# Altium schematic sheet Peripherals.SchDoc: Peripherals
size A4; Date: 01-DEC-2013; CompanyName: STMicroelectronics; Organization: Microcontrollers Division; Address1: 12, Rue Jules HOROWITZ; Address2: 38019 Grenoble; Address3: FRANCE; DocumentNumber: MB1263; Revision: C-04; SheetNumber: 11; SheetTotal: 11; Project: STM32MP157-EVAL
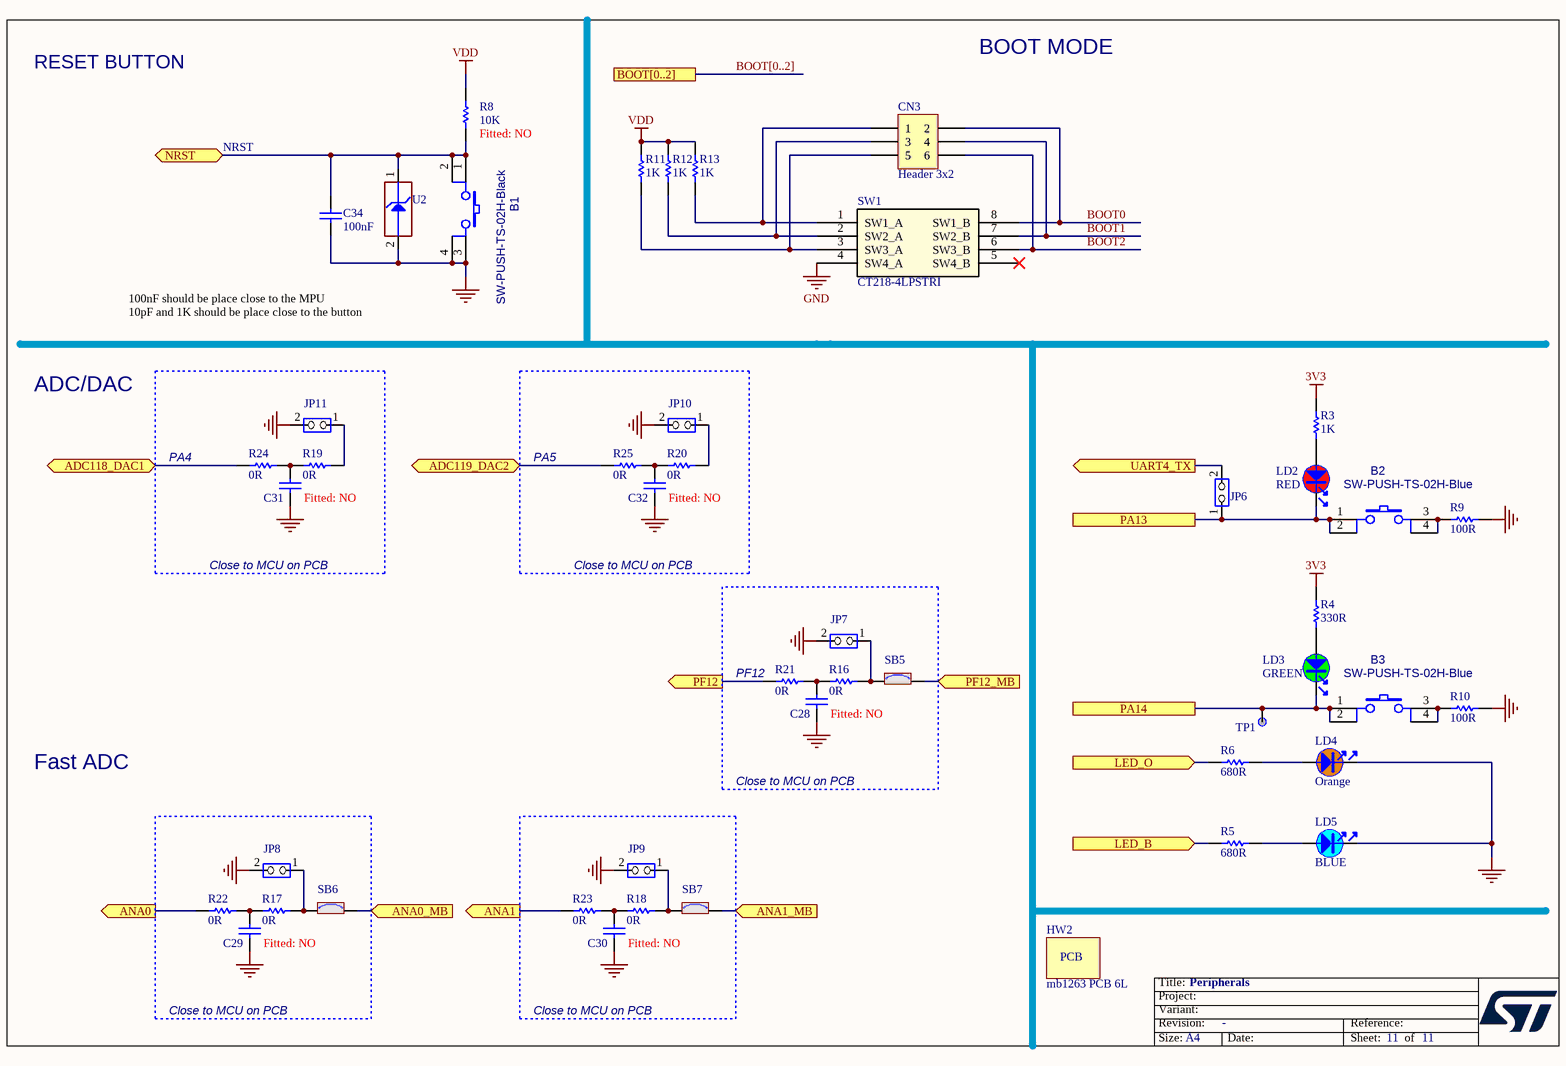
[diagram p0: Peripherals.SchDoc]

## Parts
B1  SW-PUSH-TS-02H-Black  [SWI_JIUBABA_C-TS-02H-2-5-K-V-T_R_BLACK]
B2  SW-PUSH-TS-02H-Blue  [SWI_JIUBABA_C-TS-02H-2-5-B-V-T_R_BLUE]
B3  SW-PUSH-TS-02H-Blue  [SWI_JIUBABA_C-TS-02H-2-5-B-V-T_R_BLUE]
C28  Fitted: NO  [C0402]  (hidden comment: 100nF)
C29  Fitted: NO  [C0402]  (hidden comment: 100nF)
C30  Fitted: NO  [C0402]  (hidden comment: 100nF)
C31  Fitted: NO  [C0402]  (hidden comment: 100nF)
C32  Fitted: NO  [C0402]  (hidden comment: 100nF)
C34  100nF  [C0402]
CN3  Header 3x2  [CON_SAMTEC_TSW-103-07-X-D]
HW2  mb1263 PCB 6L  (mechanical)
JP6  Jumper_2.54mm  [CON_SAMTEC_TSW-102-07-G-S]  (value not drawn)
JP7  Jumper_2.54mm  [CON_SAMTEC_TSW-102-07-G-S]  (value not drawn)
JP8  Jumper_2.54mm  [CON_SAMTEC_TSW-102-07-G-S]  (value not drawn)
JP9  Jumper_2.54mm  [CON_SAMTEC_TSW-102-07-G-S]  (value not drawn)
JP10  Jumper_2.54mm  [CON_SAMTEC_TSW-102-07-G-S]  (value not drawn)
JP11  Jumper_2.54mm  [CON_SAMTEC_TSW-102-07-G-S]  (value not drawn)
LD2  value RED  [LED_0603_RED]  (hidden comment: LED_red)
LD3  value GREEN  [LED_0603_GREEN]  (hidden comment: LED_green)
LD4  value Orange  [LED_0603_ORANGE_H0P4]  (hidden comment: LED_orange)
LD5  value BLUE  [LED_0603_SMD-B_BLUE_H0P4]  (hidden comment: LED_blue)
R3  1K  [R0402]
R4  330R  [R0402]
R5  value 680R  [R0402]  (hidden comment: Resistor)
R6  value 680R  [R0402]  (hidden comment: Resistor)
R8  10K  Fitted: NO  [R0402]
R9  100R  [R0402]
R10  100R  [R0402]
R11  1K  [R0402]
R12  1K  [R0402]
R13  1K  [R0402]
R16  0R  [R0402]
R17  0R  [R0402]
R18  0R  [R0402]
R19  0R  [R0402]
R20  0R  [R0402]
R21  0R  [R0402]
R22  0R  [R0402]
R23  0R  [R0402]
R24  0R  [R0402]
R25  0R  [R0402]
SB5  SB_ON  [SOLDER-BRIDGE_R0603-0R]  (value not drawn)
SB6  SB_ON  [SOLDER-BRIDGE_R0603-0R]  (value not drawn)
SB7  SB_ON  [SOLDER-BRIDGE_R0603-0R]  (value not drawn)
SW1  CT218-4LPSTRI  [SWI_CTS_CTS218-4LP]
TP1  TP  [TP_SMD_1MM]  (value not drawn)  (no BOM)
U2  ESDALC6V1-1U2  [ESD_ST0201]  (value not drawn)

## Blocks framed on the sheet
Close to MCU on PCB: C29 JP8 R17 R22 SB6
Close to MCU on PCB: C30 JP9 R18 R23 SB7

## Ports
ADC118_DAC1 (bidir), ADC119_DAC2 (bidir), ANA0 (out), ANA0_MB (in), ANA1 (out), ANA1_MB (in), BOOT[0..2], LED_B (in), LED_O (in), NRST (bidir), PA13, PA14, PF12 (out), PF12_MB (in), UART4_TX (out)

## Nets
3V3: R3.1 R4.2
GND: B1.3 B1.4 C28.1 C29.1 C30.1 C31.1 C32.1 C34.1 JP7.2(NO) JP8.2(NO) JP9.2(NO) JP10.2(NO) JP11.2(NO) LD4.2 LD5.2 R9.2 R10.2 SW1.4(SW4_A) U2.2(GND)
VDD: R8.2 R11.1 R12.1 R13.1
ADC118_DAC1: R24.1 ; port ADC118_DAC1
ADC119_DAC2: R25.1 ; port ADC119_DAC2
ANA0: R22.1 ; port ANA0
ANA0_MB: SB6.2 ; port ANA0_MB
ANA1: R23.1 ; port ANA1
ANA1_MB: SB7.2 ; port ANA1_MB
BOOT0: CN3.2 SW1.8(SW1_B)
BOOT1: CN3.4 SW1.7(SW2_B)
BOOT2: CN3.6 SW1.6(SW3_B)
LED_B: R5.1 ; port LED_B
LED_O: R6.1 ; port LED_O
NRST: B1.1 B1.2 C34.2 R8.1 U2.1(IO1) ; port NRST
PA13: B2.1 B2.2 JP6.1(COMMON) LD2.2 ; port PA13
PA14: B3.1 B3.2 LD3.2 TP1.1 ; port PA14
PF12: R21.1 ; port PF12
PF12_MB: SB5.2 ; port PF12_MB
UART4_TX: JP6.2(NO) ; port UART4_TX
NetB2_3: B2.3 B2.4 R9.1
NetB3_3: B3.3 B3.4 R10.1
NetC28_2: C28.2 R16.1 R21.2
NetC29_2: C29.2 R17.1 R22.2
NetC30_2: C30.2 R18.1 R23.2
NetC31_2: C31.2 R19.1 R24.2
NetC32_2: C32.2 R20.1 R25.2
NetCN3_1: CN3.1 R13.2 SW1.1(SW1_A)
NetCN3_3: CN3.3 R12.2 SW1.2(SW2_A)
NetCN3_5: CN3.5 R11.2 SW1.3(SW3_A)
NetJP7_1: JP7.1(COMMON) R16.2 SB5.1
NetJP8_1: JP8.1(COMMON) R17.2 SB6.1
NetJP9_1: JP9.1(COMMON) R18.2 SB7.1
NetJP10_1: JP10.1(COMMON) R20.2
NetJP11_1: JP11.1(COMMON) R19.2
NetLD2_1: LD2.1 R3.2
NetLD3_1: LD3.1 R4.1
NetLD4_1: LD4.1 R6.2
NetLD5_1: LD5.1 R5.2

Not connected (* = marked no-connect by the designer): SW1 5(SW4_B)*

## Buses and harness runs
bus BOOT[0..2] = port BOOT[0..2]

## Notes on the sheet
- BOOT MODE
- RESET BUTTON
- NRST
- 100nF should be place close to the MPU
  10pF and 1K should be place close to the button
- ADC/DAC
- PA4
- PA5
- Close to MCU on PCB
- (near R21) PF12
- Fast ADC

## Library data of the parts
B1 = SW-PUSH-TS-02H-Black: TS-02H SMD Light Touch Switch black; Manuf_1: Jiubaba; Manuf_Part_1: C-TS-02H-2.5-K-V-T/R BLACK; Fitted: YES; Ordered_By: Subcon
B2 B3 = SW-PUSH-TS-02H-Blue: TS-02H SMD Light Touch Switch blue; Manuf_1: Jiubaba; Manuf_Part_1: C-TS-02H-2.5-K-V-T/R BLUE; Ordered_By: Subcon; Fitted: YES
C28-C32 = Cap_100nF_X7R_10%_0402: Capacitor,100nF,16V,X7R,10%,0402,YAGEO; Manuf_Part_1: CC0402KRX7R7BB104; Ordered_By: Subcon
C34 = Cap_100nF_X7R_10%_0402: Capacitor,100nF,16V,X7R,10%,0402,YAGEO; Manuf_Part_1: CC0402KRX7R7BB104; Fitted: YES; Ordered_By: Subcon
CN3 = Header 3x2: Header, 3x2, 2,54mm, VR, TH, Height 5.84mm/2.54mm; Manuf_Part_1: TSW-103-07-x-D; Manuf_1: SAMTEC; Fitted: YES; Ordered_By: Subcon
HW2 = PCB_mb1263: Fitted: YES; Ordered_By: Subcon
JP6-JP11 = TSW-102-07-x-S: Connector jumper 1 position; Manuf_1: SAMTEC; Manuf_Part_2: 4711955140470; Manuf_2: KONTEC; Order_Code: 423-2841; Fitted: YES; Ordered_By: Subcon
LD2 = MCD-02899: LED, Red, VF : Min=1.75V , Max=2.35V, 25mA, 0603; Part_Type: Display; Part_Preference: Recommended; Manufacturer: EVERLIGHT; Manufacturer_Part_Number: 19-213/R6C-AP1Q2B/5T; Full_Alternate_Internal_Part_Number: MCD-00049; Component_Country_Of_Origin: China; ShowFields: YES; ID: 5015
LD3 = MCD-02900: LED, Green, 2V, 25mA, 0603, SMD; Part_Type: Display; Part_Preference: Recommended; Manufacturer: EVERLIGHT; Manufacturer_Part_Number: 19-213SYGC/S530-E2/5T; Full_Alternate_Internal_Part_Number: MCD-00320; Partial_Alternate_Internal_Part_Number: MCD-00050; Component_Country_Of_Origin: China; ShowFields: YES; ID: 5016
LD4 = MCD-02785: LED, Orange, VF: Min=1.7V, Max=2.2V, 25mA, 0603; Part_Type: Display; Part_Preference: Recommended; Manufacturer: EVERLIGHT; Manufacturer_Part_Number: 19-217/S2C-AM2N2VY/6T; Full_Alternate_Internal_Part_Number: MCD-00321; Component_Country_Of_Origin: China; ShowFields: YES; ID: 4897
LD5 = MCD-02786: LED, Blue, VF: Min=2.5V, Max=3.1V, 10mA, 0603; Part_Type: Display; Part_Preference: Recommended; Manufacturer: EVERLIGHT; Manufacturer_Part_Number: 19-217/BHC-ZL1M2RY/6T; Full_Alternate_Internal_Part_Number: MCD-01131; Component_Country_Of_Origin: China; ShowFields: YES; ID: 4898
R3 R11-R13 = Res_1K_1%_0402: Resistor,1K,0402,1%,YAGEO; Manuf_Part_1: RC0402FR-071KL; Fitted: YES; Ordered_By: Subcon
R4 = Res_330_1%_0402: Resistor,330R,0402,1%,YAGEO; Manuf_Part_1: RC0402FR-07330RL; Fitted: YES; Ordered_By: Subcon
R5 R6 = Res_680R_1%_0402: Resistor,680R,0402,1%,1/16W; Manuf_Part_1: RC0402FR-07680RL; Manuf_1: YAGEO; Ordered_By: Subcon; Fitted: YES
R8 = Res_10K_1%_0402: Resistor,10K,0402,1%,YAGEO; Manuf_Part_1: RC0402FR-0710KL; Ordered_By: subcon
R9 R10 = Res_100_1%_0402: Resistor,100R,0402,1%,YAGEO; Manuf_Part_1: RC0402FR-07100RL; Order_Code: 9239111; Fitted: YES; Ordered_By: Subcon
R16-R25 = Res_0_5%_0402: Resistor,0R,0402,5%,YAGEO; Manuf_Part_1: RC0402JR-070RL; Order_Code: 2363467; Fitted: YES; Ordered_By: Subcon
SB5-SB7 = SB_ON: Solder Bridge ON; Fitted: YES; Ordered_by: Subcon
SW1 = SWITCH_4WAY: Quad SPST surface mount switch. 1.27mm pitch. Tinned legs.; Part_Type: SWITCH; Manuf_1: CTS; Fitted: YES; Ordered_By: Subcon
TP1 = TP 1mm: Test Point; Fitted: YES
U2 = ESDALC6V1-1U2: ESD protection 6V1; Part_Type: Diode; Manuf_1: STMICROELECTRONICS; ECCN_US: EAR99; ECCN_EU: NEC; Ordered_By: Subcon; Fitted: YES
